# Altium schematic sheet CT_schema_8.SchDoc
size 391 x 238 mm
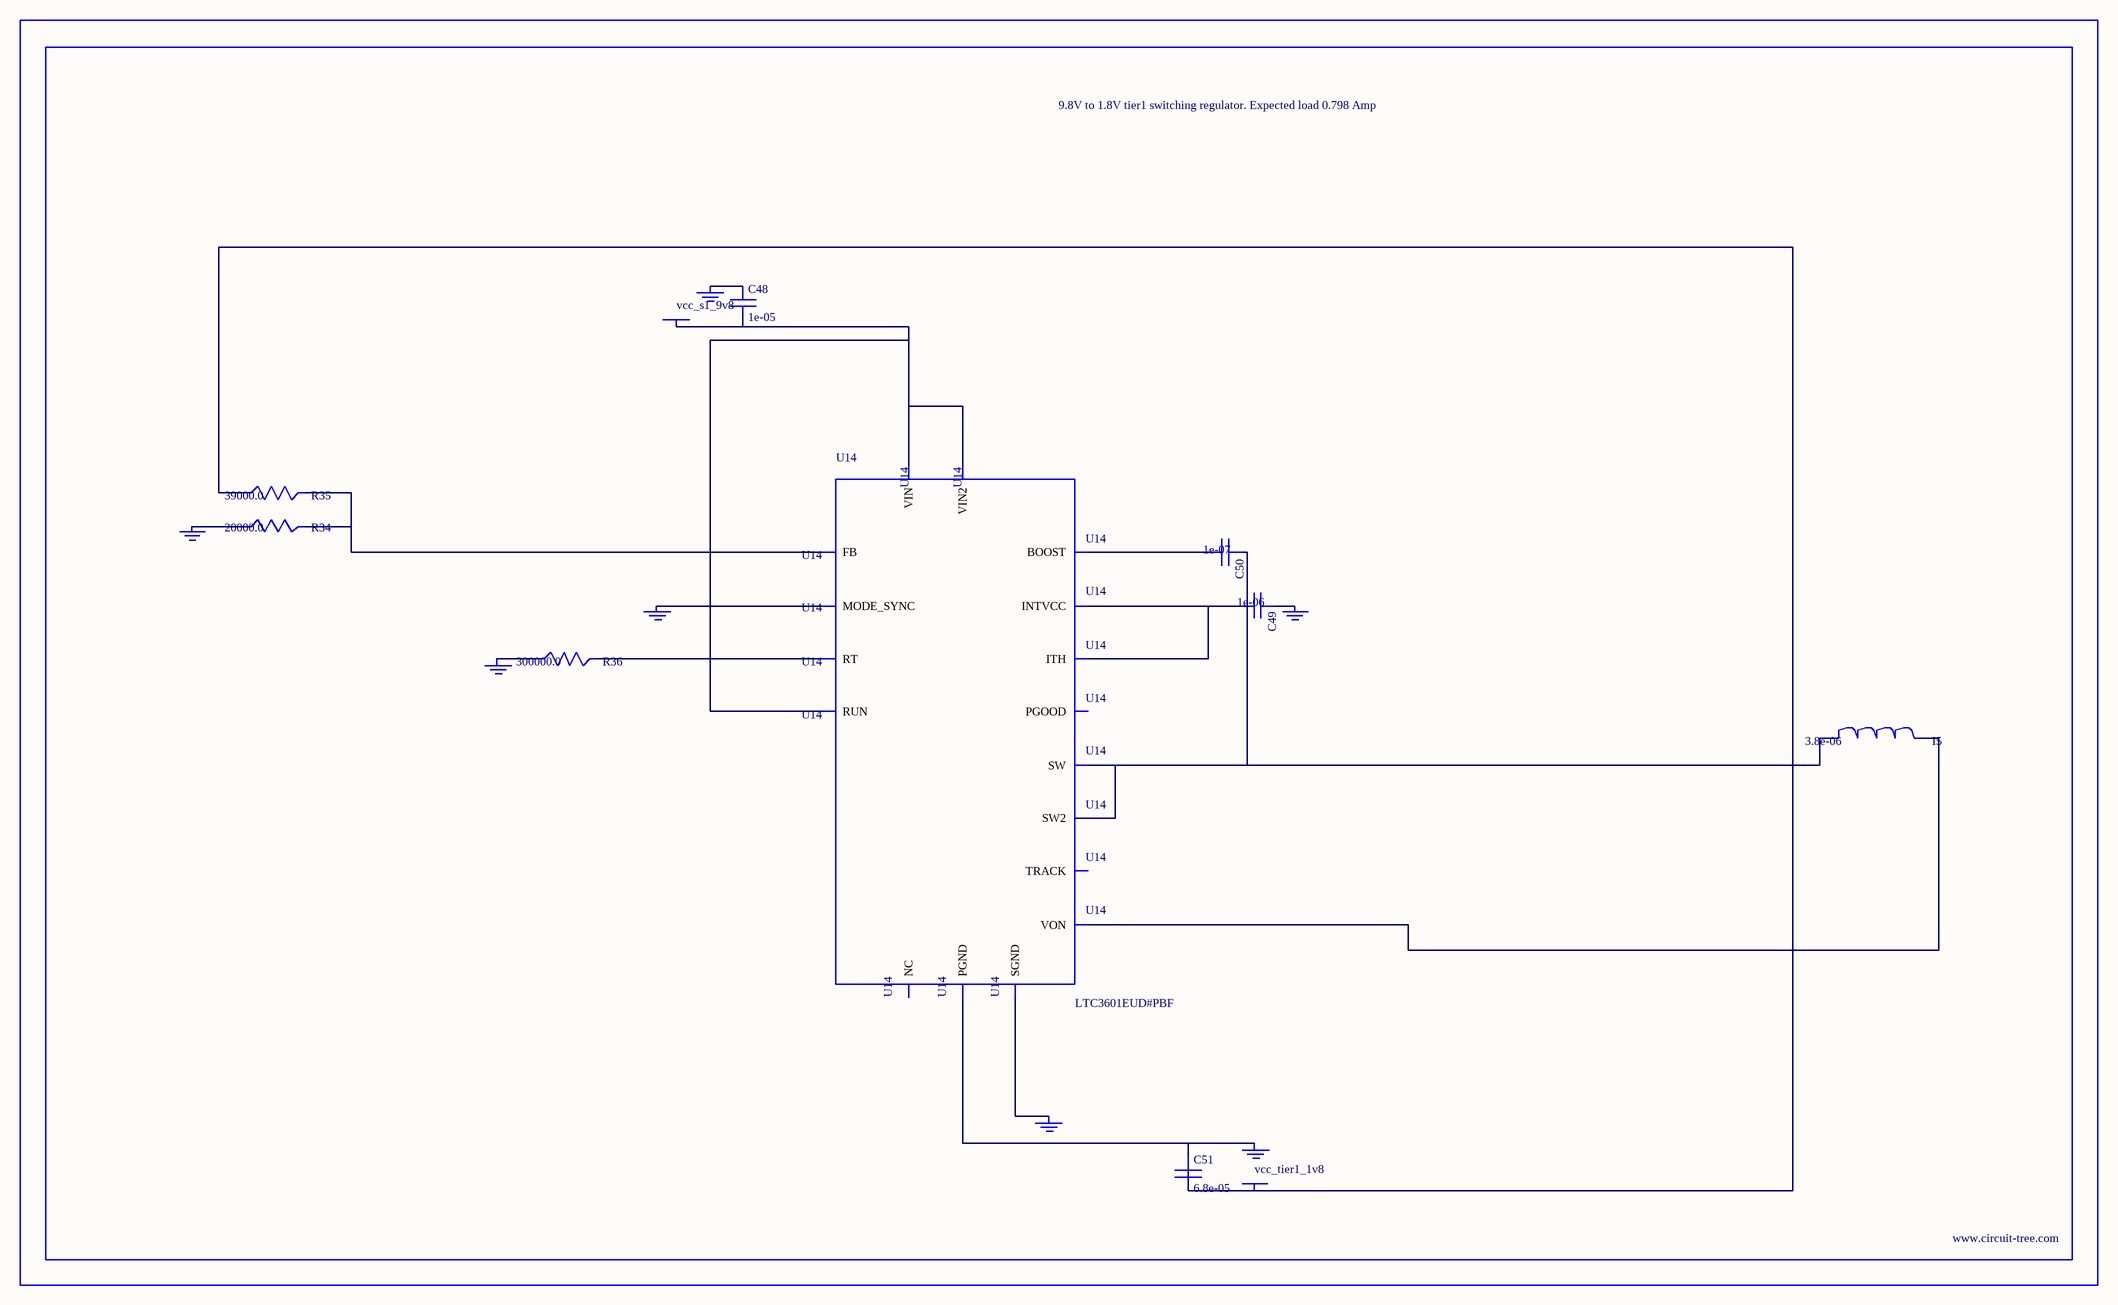
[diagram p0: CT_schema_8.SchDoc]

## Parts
BORDER7  (no value)
C48  1e-05  [C0805]
C49  1e-06  [C0603]
C50  1e-07  [C0402]
C51  6.8e-05  [2220]
GND_INSTANCE_7_0  (no value)
GND_INSTANCE_7_1  (no value)
GND_INSTANCE_7_2  (no value)
GND_INSTANCE_7_3  (no value)
GND_INSTANCE_7_4  (no value)
GND_INSTANCE_7_5  (no value)
GND_INSTANCE_7_6  (no value)
I5  3.8e-06  [DR1040]
POWER_INSTANCE_7_0  vcc_s1_9v8
POWER_INSTANCE_7_1  vcc_tier1_1v8
R34  20000.0  [R0603]
R35  39000.0  [R0603]
R36  300000.0  [R0603]
U14  LTC3601EUD#PBF  [QFN-16_EP]

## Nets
NetC48_1: C48.1 GND_INSTANCE_7_5.0(GND)
NetC48_2: C48.2 POWER_INSTANCE_7_0.0(PWR) U14.14(RUN) U14.15(VIN) U14.16(VIN2)
NetC49_1: C49.1 GND_INSTANCE_7_1.0(GND)
NetC49_2: C49.2 U14.7(INTVCC) U14.12(ITH)
NetC50_1: C50.1 I5.1 U14.3(SW) U14.4(SW2)
NetC50_2: C50.2 U14.6(BOOST)
NetC51_1: C51.1 GND_INSTANCE_7_6.0(GND) U14.17(PGND)
NetC51_2: C51.2 I5.2 POWER_INSTANCE_7_1.0(PWR) R35.1 U14.8(VON)
NetGND_INSTANCE_7_0_0: GND_INSTANCE_7_0.0(GND) U14.1(MODE_SYNC)
NetGND_INSTANCE_7_2_0: GND_INSTANCE_7_2.0(GND) U14.9(SGND)
NetGND_INSTANCE_7_3_0: GND_INSTANCE_7_3.0(GND) R36.1
NetGND_INSTANCE_7_4_0: GND_INSTANCE_7_4.0(GND) R34.1
NetR34_2: R34.2 R35.2 U14.11(FB)
NetR36_2: R36.2 U14.10(RT)

Not connected (* = marked no-connect by the designer): U14 2(PGOOD) 5(NC) 13(TRACK)

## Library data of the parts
BORDER7 = BORDER_PAGE7
C48 = C0805C106K8RACTU
C49 = C0603C105K3RACTU
C50 = C0402C104K3RACTU
C51 = C5750X5R1A686M
GND_INSTANCE_7_0-GND_INSTANCE_7_6 = GND
I5 = DR1040-3R8-R
POWER_INSTANCE_7_0 POWER_INSTANCE_7_1 = PWR
R34 = RC0603JR-0720KL
R35 = RC0603JR-0739KL
R36 = RC0603JR-07300KL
